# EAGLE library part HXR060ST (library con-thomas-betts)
THOMAS&BETTS
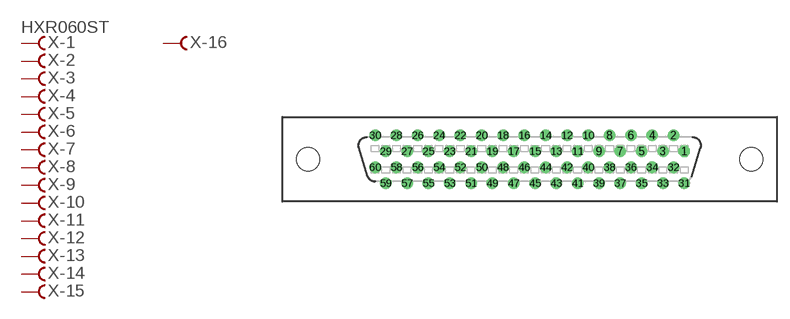
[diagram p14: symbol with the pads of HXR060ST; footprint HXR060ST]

Designator prefix X; gates -1=FV -2=F -3=F -4=F -5=F -6=F -7=F -8=F -9=F -10=F -11=F -12=F -13=F -14=F -15=F -16=F -17=F -18=F -19=F -20=F -21=F -22=F -23=F -24=F -25=F -26=F -27=F -28=F -29=F -30=F -31=F -32=F -33=F -34=F -35=F -36=F -37=F -38=F -39=F -40=F -41=F -42=F -43=F -44=F -45=F -46=F -47=F -48=F -49=F -50=F -51=F -52=F -53=F -54=F -55=F -56=F -57=F -58=F -59=F -60=F

## HXR060ST (OC_FARNELL: unknown; OC_NEWARK: unknown)  [HXR060ST]
1  -1:F  pas
2  -2:F  pas
3  -3:F  pas
4  -4:F  pas
5  -5:F  pas
6  -6:F  pas
7  -7:F  pas
8  -8:F  pas
9  -9:F  pas
10  -10:F  pas
11  -11:F  pas
12  -12:F  pas
13  -13:F  pas
14  -14:F  pas
15  -15:F  pas
16  -16:F  pas
17  -17:F  pas
18  -18:F  pas
19  -19:F  pas
20  -20:F  pas
21  -21:F  pas
22  -22:F  pas
23  -23:F  pas
24  -24:F  pas
25  -25:F  pas
26  -26:F  pas
27  -27:F  pas
28  -28:F  pas
29  -29:F  pas
30  -30:F  pas
31  -31:F  pas
32  -32:F  pas
33  -33:F  pas
34  -34:F  pas
35  -35:F  pas
36  -36:F  pas
37  -37:F  pas
38  -38:F  pas
39  -39:F  pas
40  -40:F  pas
41  -41:F  pas
42  -42:F  pas
43  -43:F  pas
44  -44:F  pas
45  -45:F  pas
46  -46:F  pas
47  -47:F  pas
48  -48:F  pas
49  -49:F  pas
50  -50:F  pas
51  -51:F  pas
52  -52:F  pas
53  -53:F  pas
54  -54:F  pas
55  -55:F  pas
56  -56:F  pas
57  -57:F  pas
58  -58:F  pas
59  -59:F  pas
60  -60:F  pas

## Footprint HXR060ST (pad centres in mm)
THOMAS&BETTS HFR060ST29xx, HHR060ST29xx
drill 0.864 octagon: 1 18.415,0.953
drill 0.864 round: 2 17.145,2.857; 3 15.875,0.953; 4 14.605,2.857; 5 13.335,0.953; 6 12.065,2.857; 7 10.795,0.953; 8 9.525,2.857; 9 8.255,0.953; 10 6.985,2.857; 11 5.715,0.953; 12 4.445,2.857; 13 3.175,0.953; 14 1.905,2.857; 15 0.635,0.953; 16 -0.635,2.857; 17 -1.905,0.953; 18 -3.175,2.857; 19 -4.445,0.953; 20 -5.715,2.857; 21 -6.985,0.953; 22 -8.255,2.857; 23 -9.525,0.953; 24 -10.795,2.857; 25 -12.065,0.953; 26 -13.335,2.857; 27 -14.605,0.953; 28 -15.875,2.857; 29 -17.145,0.953; 30 -18.415,2.857; 31 18.415,-2.857; 32 17.145,-0.953; 33 15.875,-2.857; 34 14.605,-0.953; 35 13.335,-2.857; 36 12.065,-0.953; 37 10.795,-2.857; 38 9.525,-0.953; 39 8.255,-2.857; 40 6.985,-0.953; 41 5.715,-2.857; 42 4.445,-0.953; 43 3.175,-2.857; 44 1.905,-0.953; 45 0.635,-2.857; 46 -0.635,-0.953; 47 -1.905,-2.857; 48 -3.175,-0.953; 49 -4.445,-2.857; 50 -5.715,-0.953; 51 -6.985,-2.857; 52 -8.255,-0.953; 53 -9.525,-2.857; 54 -10.795,-0.953; 55 -12.065,-2.857; 56 -13.335,-0.953; 57 -14.605,-2.857; 58 -15.875,-0.953; 59 -17.145,-2.857; 60 -18.415,-0.953
hole 2.769 at 26.416,0.013
hole 2.769 at -26.416,0.013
